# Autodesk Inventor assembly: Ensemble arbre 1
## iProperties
Shininess: 60.0
Length Units: 11269
Angle Units: 11279
Time Units: 11290
Mass Units: 11283
Length Display Precision: 3
Angle Display Precision: 2
Created: 2000-10
Part Number: Ensemble arbre 1
Document SubType Name: Assemblage
Density: 1.0
Volumn: 154.13544653399086
Area: 573.602030198532
PropertySet Name: Model Information
Control State: 0
Master: False
Checked Out: False
Author: Laurent GAUTHERON
